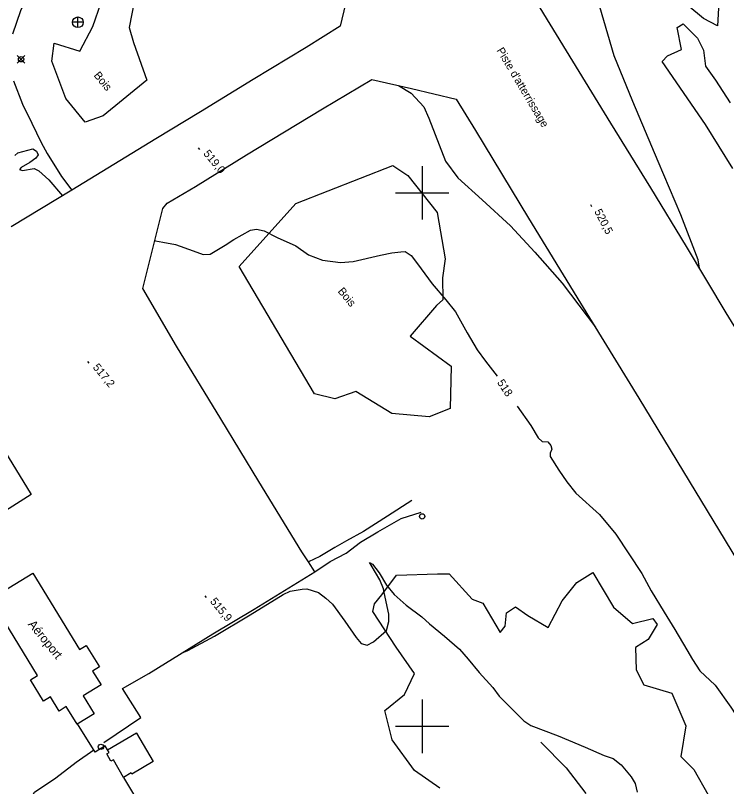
# Model space of a CAD drawing. Extents: x 347312 to 350503, y 6073086 to 6076432.
# Drawn here: x 349347.5 to 349614.2, y 6074777.4 to 6075066.4 of the extents above; entities that cross this region are included whole.
import ezdxf

# ---------------------------------------------------------------- set-up
doc = ezdxf.new("R2010")
doc.units = 0
for name, color, linetype in [('Level 1', 7, 'Continuous'), ('Level 16', 7, 'Continuous'), ('Level 19', 7, 'Continuous'), ('Level 2', 7, 'Continuous'), ('Level 22', 7, 'Continuous'), ('Level 25', 7, 'Continuous'), ('Level 3', 7, 'Continuous'), ('Level 31', 7, 'Continuous'), ('Level 36', 7, 'Continuous'), ('Level 37', 7, 'Continuous'), ('Level 4', 7, 'Continuous'), ('Level 44', 7, 'Continuous'), ('Level 61', 7, 'Continuous')]:
    doc.layers.add(name, color=color, linetype=linetype)

msp = doc.modelspace()

# ---------------------------------------------------------------- linework, layer by layer
at = {"layer": 'Level 1'}
for points in [[(349604.03, 6074971.68), (349603.49, 6074974.84), (349597.09, 6074991.67), (349588.58, 6075011.64), (349579.1, 6075034.21), (349572.04, 6075051.31), (349565.85, 6075072.85), (349558.38, 6075089.2), (349548.3, 6075106.62), (349538.13, 6075119.3), (349525.55, 6075140.33), (349515.69, 6075157.94), (349503.8, 6075177.26), (349490.58, 6075196.11), (349474.22, 6075217.44)], [(349491.15, 6075040.17), (349495.96, 6075037.32), (349500.67, 6075032.15), (349502.61, 6075027.97), (349508.83, 6075011.79), (349513.4, 6075005.61), (349522.58, 6074997.28), (349533.13, 6074987.55), (349542.24, 6074977.67), (349552.57, 6074966.12), (349565.03, 6074949.56)]]:
    msp.add_lwpolyline(points, dxfattribs=at)
at = {"layer": 'Level 16'}
for p, q in [((349372.95, 6075063.89), (349368.95, 6075063.89)), ((349370.95, 6075061.89), (349370.95, 6075065.89))]:
    msp.add_line(p, q, dxfattribs=at)
msp.add_circle((349370.96, 6075063.88), 2, dxfattribs=at)
at = {"layer": 'Level 19'}
for points in [[(349496.22, 6074884.58), (349487.05, 6074878.82), (349478.11, 6074872.96), (349471.72, 6074869.54), (349467.36, 6074867.01), (349461.67, 6074863.65), (349457.38, 6074861.63)], [(349459.75, 6074857.96), (349465.56, 6074861.72), (349471.53, 6074864.93), (349476.95, 6074868.97), (349483.47, 6074872.87), (349492.16, 6074877.85), (349499.64, 6074880.22)], [(349347.94, 6074757.16), (349351.63, 6074766.38), (349353.94, 6074773.92), (349354.72, 6074775.33), (349362.69, 6074780.75), (349370.36, 6074786.61), (349376.87, 6074791.25)]]:
    msp.add_lwpolyline(points, dxfattribs=at)
at = {"layer": 'Level 2'}
for points in [[(349347.33, 6075013.95), (349348.49, 6075014.96), (349354.05, 6075016.4), (349355.37, 6075015.51), (349356.01, 6075014.16), (349355.2, 6075012.91), (349352.99, 6075011.38), (349349.74, 6075009.5), (349349.1, 6075008.67), (349350.18, 6075008.38), (349354.51, 6075009.03), (349356.35, 6075008.18), (349360.07, 6075004.87), (349365.21, 6074998.85)], [(349399.83, 6074982.05), (349400.05, 6074982.02), (349402.78, 6074981.48), (349407.6, 6074980.65), (349414.2, 6074978.24), (349417.89, 6074976.83), (349420.59, 6074977.01), (349426.12, 6074980.34), (349429.45, 6074982.44), (349435.64, 6074985.94), (349437.91, 6074986.3), (349440.78, 6074985.67), (349445.7, 6074983.15), (349452.69, 6074980.14), (349457.48, 6074976.69), (349462.73, 6074974.74), (349469.42, 6074973.78), (349474.24, 6074974.18), (349484.41, 6074976.54), (349488.67, 6074977.41), (349492.11, 6074977.84), (349493.72, 6074978.02), (349495.87, 6074976.49), (349498.27, 6074973.28), (349503.81, 6074965.87), (349508.93, 6074959.86), (349512.56, 6074955.41), (349516.9, 6074947.5), (349520.69, 6074941.15), (349523.81, 6074936.81), (349528.13, 6074931.19)], [(349535.73, 6074920.04), (349540.8, 6074912.75), (349543.61, 6074908.14), (349545.05, 6074906.81), (349547.21, 6074906.67)], [(349547.21, 6074906.67), (349548.35, 6074905.22), (349548.7, 6074903.89), (349548.02, 6074902.34), (349548.01, 6074901.11), (349551.3, 6074895.96), (349554.27, 6074891.63), (349557.62, 6074887.34), (349566.59, 6074879.43), (349572.62, 6074872.07), (349577.49, 6074864.64), (349582.44, 6074857.28), (349585.93, 6074850.82), (349590.83, 6074842.75), (349594.75, 6074836.26), (349599.32, 6074828.71), (349601.47, 6074825.02), (349604.23, 6074820.78), (349609.88, 6074815.41), (349615.85, 6074807.2), (349622.74, 6074796.39), (349627.87, 6074787.58), (349632.5, 6074779.82), (349637.66, 6074772.54)], [(349450.53, 6074850.69), (349455.04, 6074851.39), (349456.85, 6074851.48), (349461.16, 6074850.1), (349463.91, 6074848.03), (349466.43, 6074845.77), (349471, 6074839.47), (349475.35, 6074833.26), (349477.16, 6074831.05), (349479.49, 6074830.38), (349481.81, 6074831.73), (349486.62, 6074835.94), (349487.56, 6074839.33), (349487.52, 6074841.99), (349485.81, 6074850.16), (349485.61, 6074851.48), (349484.15, 6074854.85), (349480.95, 6074860.36), (349480.3, 6074861.42), (349481.49, 6074860.84), (349483.89, 6074857.48), (349486.65, 6074852.94), (349489.61, 6074849.4), (349494.07, 6074845.4), (349499.96, 6074841.02), (349502.77, 6074838.43), (349508.43, 6074833.85), (349513.99, 6074828.91), (349517.3, 6074825.13), (349521.48, 6074820.21), (349526.55, 6074814.57), (349528.88, 6074811.3), (349534.26, 6074805.94), (349538.15, 6074802.12), (349540.86, 6074800.28), (349550.99, 6074796.49), (349554.87, 6074794.86), (349561.15, 6074792.2), (349568.27, 6074789.04), (349571.68, 6074787.95), (349574.71, 6074785.58), (349578.48, 6074781.12), (349579.98, 6074778.63), (349580.71, 6074775.32)], [(349409.85, 6074827.43), (349412.14, 6074828.45), (349422.18, 6074833.79), (349435.53, 6074841.8), (349447.92, 6074849.36), (349450.53, 6074850.69)]]:
    msp.add_lwpolyline(points, dxfattribs=at)
at = {"layer": 'Level 22'}
for points in [[(349463.96, 6075115.56), (349453.6, 6075109.67), (349442.09, 6075105.27), (349433.45, 6075103.75), (349421.94, 6075102.98), (349403.48, 6075102.28), (349387.89, 6075100.89), (349384.88, 6075100.17), (349382.21, 6075099.05), (349378.55, 6075096.58), (349373.26, 6075093.63), (349364.35, 6075088.7), (349360.29, 6075086.26), (349357.62, 6075084.32), (349355.71, 6075082.1), (349352.94, 6075075.37), (349349.47, 6075068.12), (349346.48, 6075059.39)], [(349346.77, 6075041.99), (349350.19, 6075033.21), (349353.64, 6075026.05), (349357.16, 6075018.79), (349359.41, 6075014.71), (349364.86, 6075006.12), (349368.66, 6075000.94)]]:
    msp.add_lwpolyline(points, dxfattribs=at)
at = {"layer": 'Level 25'}
for points in [[(349721.53, 6074778.43), (349696.21, 6074820.32), (349678.53, 6074848.95), (349661.66, 6074876.79), (349648.66, 6074898.31), (349631.08, 6074927.35), (349614, 6074955), (349599.14, 6074979.85), (349585.75, 6075001.78), (349570.8, 6075026.04), (349554.23, 6075053.21), (349538.16, 6075079.35), (349521.5, 6075107.01), (349504.56, 6075134.66), (349486.92, 6075164.05), (349469.94, 6075191.95), (349455.63, 6075215.23), (349434.44, 6075249.99), (349417.82, 6075277.49), (349398.78, 6075308.89), (349378.79, 6075341.9), (349366.14, 6075362.44), (349352, 6075385.86), (349336.82, 6075410.53)], [(349330.66, 6075334.49), (349350.11, 6075302.45), (349365.7, 6075276.73), (349378.86, 6075254.66), (349394.02, 6075230.3), (349408.72, 6075206.12), (349426.04, 6075177.6), (349441.28, 6075152.62), (349453.47, 6075132.64), (349463.96, 6075115.56), (349465.34, 6075113.32), (349477.05, 6075094.13), (349472.68, 6075076.62), (349469.3, 6075062.36), (349456.5, 6075054.45), (349436.63, 6075042.39), (349416.91, 6075030.32), (349400.15, 6075020.2), (349368.66, 6075000.94), (349345.97, 6074987.19)], [(349380.67, 6074793.89), (349394.5, 6074803.27), (349387.67, 6074814.12), (349397.5, 6074819.82), (349421.54, 6074834.63), (349437, 6074843.86), (349459.75, 6074857.96), (349457.38, 6074861.63), (349454.99, 6074865.34), (349438.78, 6074891.74), (349424.57, 6074915.27), (349407.97, 6074942.52), (349395.32, 6074964.07), (349402.85, 6074994.07), (349404.46, 6074996.11), (349415.07, 6075002.32), (349434.14, 6075014.15), (349462.68, 6075031.39), (349481.14, 6075042.41), (349496, 6075039.08), (349512.84, 6075035.07), (349520.07, 6075023.29), (349539.95, 6074990.52), (349559.48, 6074958.63), (349581.29, 6074923), (349600.2, 6074891.88), (349620.41, 6074858.47)], [(349340.55, 6074907.8), (349353.39, 6074886.87), (349340.88, 6074879.05)]]:
    msp.add_lwpolyline(points, dxfattribs=at)
at = {"layer": 'Level 3'}
for p, q in [((349416.02, 6075016.8), (349416.53, 6075016.18)), ((349563.22, 6074995.56), (349563.59, 6074994.85)), ((349374.56, 6074936.7), (349375.07, 6074936.08)), ((349418.55, 6074848.95), (349419.06, 6074848.33))]:
    msp.add_line(p, q, dxfattribs=at)
at = {"layer": 'Level 31'}
for points in [[(349379.66, 6074815.51), (349372.97, 6074811.43), (349377.08, 6074804.7), (349370.65, 6074800.77), (349366.61, 6074807.38), (349363.91, 6074805.73), (349360.66, 6074811.04), (349358.01, 6074809.42), (349353.14, 6074817.38), (349355.78, 6074819), (349338.21, 6074847.73), (349354.02, 6074857.4), (349371.55, 6074828.75), (349374.09, 6074830.31), (349379, 6074822.28), (349376.47, 6074820.73), (349379.66, 6074815.51)], [(349392.92, 6074797.48), (349399.19, 6074786.76), (349391.21, 6074782.09), (349390.95, 6074782.53), (349388.11, 6074780.87), (349384.26, 6074787.44), (349383.36, 6074786.91), (349381.75, 6074789.66), (349382.7, 6074790.21), (349382.11, 6074791.23), (349392.89, 6074797.54), (349392.92, 6074797.48)]]:
    msp.add_lwpolyline(points, dxfattribs=at)
at = {"layer": 'Level 36'}
for p, q in [((349348.23, 6075048.6), (349351.05, 6075051.42)), ((349348.23, 6075051.42), (349351.05, 6075048.6))]:
    msp.add_line(p, q, dxfattribs=at)
for centre in [(349349.64, 6075050.01), (349500.05, 6074878.68), (349379.59, 6074792.31)]:
    msp.add_circle(centre, 1, dxfattribs=at)
at = {"layer": 'Level 37'}
for points in [[(349382.11, 6074791.23), (349381.12, 6074792.67), (349377.46, 6074790.34), (349370.84, 6074800.89)], [(349404.74, 6074753.51), (349396.57, 6074766.87), (349389.74, 6074778.36), (349388.13, 6074780.88)]]:
    msp.add_lwpolyline(points, dxfattribs=at)
at = {"layer": 'Level 4'}
msp.add_lwpolyline([(349544.61, 6074794.06), (349554.08, 6074784.43), (349561.42, 6074774.82)], dxfattribs=at)
at = {"layer": 'Level 44'}
for points in [[(349391.76, 6075056.25), (349396.75, 6075042.13), (349380.42, 6075028.82), (349373.68, 6075026.47), (349366.45, 6075035.37), (349361.19, 6075049.27), (349362.07, 6075056.07), (349371.67, 6075053.1), (349376.52, 6075062.34), (349379.63, 6075071.34), (349376.21, 6075086.65), (349383.29, 6075088.08), (349389.53, 6075083.18), (349392.89, 6075076.15), (349390.16, 6075061.88), (349391.76, 6075056.25)], [(349611.36, 6075071.38), (349610.76, 6075062.58), (349605.52, 6075065.26), (349599.65, 6075070.11)], [(349616.51, 6075009.13), (349606.35, 6075025.55), (349590.11, 6075049.23), (349592, 6075051.27), (349597.35, 6075053.66), (349595.7, 6075061.91), (349597.94, 6075063.35), (349603.36, 6075057.96), (349605.5, 6075053.44), (349606.28, 6075047.48), (349609.99, 6075042.16), (349615.54, 6075033.74)], [(349459.7, 6074924.59), (349431.45, 6074972.29), (349452.73, 6074995.93), (349489.08, 6075010.25), (349494.64, 6075006.49), (349505.72, 6074992.62), (349508.65, 6074975.23), (349507.73, 6074968.13), (349507.84, 6074959.79), (349505.37, 6074957.72), (349495.58, 6074946.17), (349510.97, 6074935.05), (349510.59, 6074919.1), (349502.66, 6074916.04), (349488.72, 6074917.25), (349475.19, 6074925.44), (349467.27, 6074922.7), (349459.7, 6074924.59)], [(349506.71, 6074776.78), (349497.13, 6074783.46), (349488.81, 6074794.97), (349486.06, 6074805.89), (349493.38, 6074811.89), (349497.2, 6074819.77), (349490.36, 6074829.67), (349481.55, 6074843.04), (349482.22, 6074845.86), (349484.9, 6074849.33), (349490.38, 6074856.65), (349505.84, 6074857.16), (349510.16, 6074857.18), (349518.82, 6074847.61), (349522.84, 6074846.18), (349529.25, 6074835.17), (349531.17, 6074837.54), (349531.64, 6074842.6), (349535.1, 6074844.75), (349539.69, 6074841.55), (349547.33, 6074837), (349552.5, 6074847.06), (349558.02, 6074853.96), (349564.07, 6074857.69), (349571.82, 6074844.67), (349578.98, 6074838.53), (349586.56, 6074840.39), (349588.22, 6074838.19), (349584.78, 6074832.59), (349580.1, 6074829.56), (349580.3, 6074821.17), (349583.12, 6074815.59), (349593.64, 6074812.43), (349598.93, 6074800.23), (349597.05, 6074788.74), (349601.97, 6074783.87), (349612.72, 6074764.87)]]:
    msp.add_lwpolyline(points, dxfattribs=at)
at = {"layer": 'Level 61'}
for p, q in [((349500, 6075010), (349500, 6074990)), ((349490, 6075000), (349510, 6075000)), ((349500, 6074810), (349500, 6074790)), ((349490, 6074800), (349510, 6074800))]:
    msp.add_line(p, q, dxfattribs=at)

# ---------------------------------------------------------------- texts
at = {"layer": 'Level 2'}
msp.add_text('518', height=3, rotation=303.4764, dxfattribs=at).set_placement((349528.03, 6074928.84))
at = {"layer": 'Level 25'}
msp.add_text("Piste d'atterrissage", height=2.9999, rotation=300.6721, dxfattribs=at).set_placement((349527.85, 6075053.36))
at = {"layer": 'Level 3'}
for s, rotation, p in [('519,0', 309.5679, (349417.83, 6075014.56)), ('520,5', 297.3834, (349564.52, 6074992.99)), ('517,2', 309.5679, (349376.37, 6074934.46)), ('515,9', 309.5679, (349420.36, 6074846.71))]:
    msp.add_text(s, height=3, rotation=rotation, dxfattribs=at).set_placement(p)
at = {"layer": 'Level 31'}
msp.add_text('Aéroport', height=3.33, rotation=309.1656, dxfattribs=at).set_placement((349352.07, 6074838.17))
at = {"layer": 'Level 44'}
for p in [(349376.73, 6075043.89), (349468.23, 6074962.98)]:
    msp.add_text('Bois', height=3, rotation=309.568, dxfattribs=at).set_placement(p)

doc.saveas('drawing.dxf')
